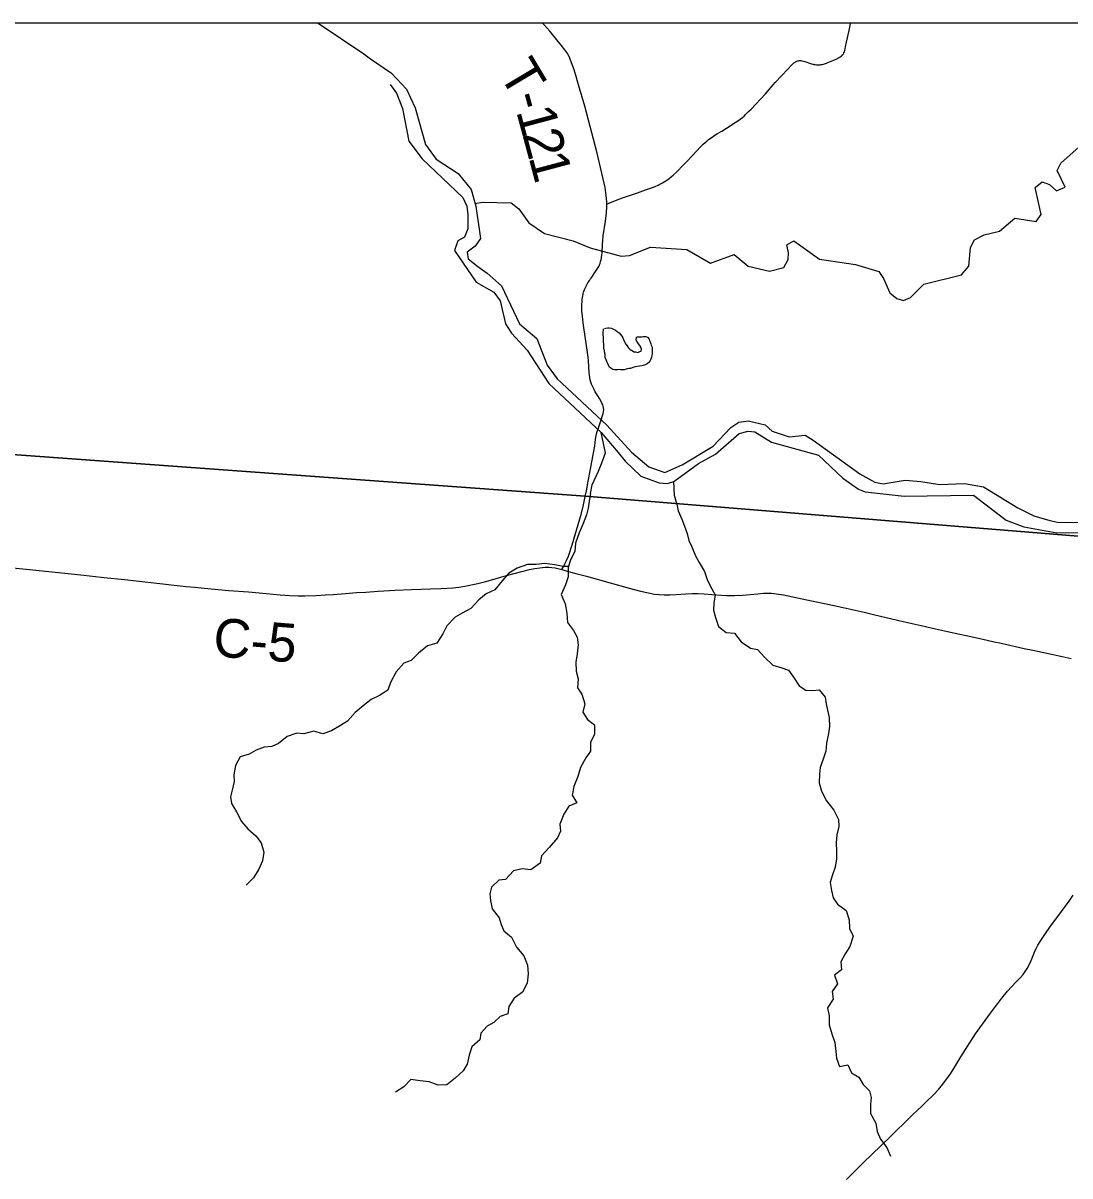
# Model space of a CAD drawing. Extents: x -1.4 to 35.4, y 0 to 22.
# Drawn here: x 6.004 to 7.544, y 18.159 to 19.855 of the extents above; entities that cross this region are included whole.
import ezdxf

# ---------------------------------------------------------------- set-up
doc = ezdxf.new("R2010")
doc.units = 0
for name, color, linetype in [('Default', 7, 'Continuous'), ('GM_X_County_Road', 7, 'Continuous'), ('GM_X_County_Road_Text', 7, 'Continuous'), ('GM_X_Major_River', 7, 'Continuous'), ('GM_X_Minor_Lake', 7, 'Continuous'), ('GM_X_Minor_River', 7, 'Continuous'), ('GM_X_Township_Road', 7, 'Continuous'), ('GM_X_Township_Road_Text', 7, 'Continuous'), ('SH_Border', 7, 'Continuous'), ('SH_Cut_Line', 7, 'Continuous')]:
    doc.layers.add(name, color=color, linetype=linetype)

msp = doc.modelspace()

# ---------------------------------------------------------------- linework, layer by layer
at = {"layer": 'Default'}
for points in [[(5.7921, 19.2341), (6.8306, 19.1588), (7.8947, 19.0723), (8.143, 19.049), (9, 18.9633), (9, 19.8546), (5.9686, 19.8546)], [(7.693, 16.8959), (7.7561, 17.6322), (7.8789, 18.9217), (7.8947, 19.0723), (6.8306, 19.1588), (5.7921, 19.2341), (4.2528, 19.417), (3.4459, 19.4989), (3.4296, 19.5001), (2.9037, 19.5459), (2.7894, 18.3098), (2.7365, 17.7956), (2.7172, 17.4718), (2.7109, 17.4025), (2.7066, 17.3545), (2.7033, 17.3163), (2.7006, 17.2849), (2.6906, 17.1666), (2.6843, 17.0961), (2.6688, 16.9164)]]:
    msp.add_lwpolyline(points, dxfattribs=at)
at = {"layer": 'GM_X_County_Road'}
for points in [[(5.9888, 19.0536), (6.0135, 19.0509), (6.0419, 19.0478), (6.0889, 19.0429), (6.1229, 19.0394), (6.1532, 19.0364), (6.1704, 19.0345), (6.205, 19.0304), (6.226, 19.028), (6.2439, 19.0261), (6.2563, 19.025), (6.2705, 19.0236), (6.3064, 19.0202), (6.3355, 19.0179), (6.3615, 19.0156), (6.3819, 19.0137), (6.3962, 19.0127), (6.4086, 19.0122), (6.4186, 19.0122), (6.4347, 19.0127), (6.449, 19.0136), (6.4602, 19.0143), (6.4781, 19.0157), (6.4942, 19.0169), (6.5079, 19.0177), (6.5265, 19.0189), (6.5512, 19.0205), (6.5754, 19.0216), (6.6026, 19.0226), (6.6187, 19.0231), (6.636, 19.0239), (6.6447, 19.0248), (6.6539, 19.0262), (6.6728, 19.0303), (6.6848, 19.0334), (6.7153, 19.042), (6.7375, 19.0481), (6.7489, 19.0509), (6.7568, 19.0525), (6.7641, 19.0535), (6.772, 19.0542), (6.7776, 19.0542), (6.7819, 19.0539), (6.7867, 19.0532), (6.7945, 19.0513), (6.7964, 19.0508)], [(6.7964, 19.0508), (6.8011, 19.0496), (6.8172, 19.0451), (6.8329, 19.041), (6.8676, 19.0315), (6.8957, 19.0237), (6.912, 19.0193), (6.9241, 19.0164), (6.9321, 19.0149), (6.9395, 19.014), (6.947, 19.0136), (6.9552, 19.0136), (6.9645, 19.0141), (6.9787, 19.0152), (6.9886, 19.0156), (6.9966, 19.0156), (7.0059, 19.0151), (7.017, 19.0141), (7.0313, 19.0131), (7.0388, 19.0128), (7.0512, 19.0128), (7.063, 19.0132), (7.0736, 19.014), (7.0847, 19.0153), (7.0933, 19.0161), (7.1007, 19.0163), (7.105, 19.0162), (7.1117, 19.0154), (7.1227, 19.0135), (7.164, 19.0048), (7.1877, 18.9998), (7.2102, 18.9949), (7.2411, 18.9881), (7.2568, 18.9844), (7.2985, 18.9746), (7.3252, 18.9686), (7.3464, 18.9637), (7.364, 18.9599), (7.3822, 18.9558), (7.3913, 18.9538), (7.4137, 18.9488), (7.4325, 18.9447), (7.4428, 18.9424), (7.4768, 18.9349), (7.4895, 18.9321), (7.5193, 18.9259), (7.546, 18.9199)], [(7.2152, 18.1538), (7.2409, 18.1791), (7.252, 18.19), (7.2666, 18.2043), (7.2796, 18.2168), (7.2885, 18.2255), (7.3004, 18.2372), (7.312, 18.2485), (7.32, 18.2562), (7.3254, 18.2614), (7.3322, 18.2678), (7.3436, 18.2791), (7.3504, 18.2864), (7.3568, 18.2939), (7.361, 18.2993), (7.3671, 18.3078), (7.3732, 18.3171), (7.379, 18.3267), (7.3835, 18.3341), (7.3936, 18.3505), (7.4053, 18.3681), (7.4153, 18.3823), (7.427, 18.3984), (7.4345, 18.4083), (7.4379, 18.4128), (7.444, 18.4206), (7.4523, 18.4307), (7.4581, 18.4372), (7.465, 18.4444), (7.4714, 18.4511), (7.475, 18.4552), (7.4783, 18.4596), (7.4812, 18.4642), (7.484, 18.4696), (7.4868, 18.4757), (7.4919, 18.4883), (7.4942, 18.4934), (7.4968, 18.4984), (7.501, 18.5053), (7.5069, 18.5142), (7.5145, 18.5248), (7.5315, 18.5478), (7.5429, 18.5633), (7.5488, 18.572)]]:
    msp.add_lwpolyline(points, dxfattribs=at)
at = {"layer": 'GM_X_Major_River'}
for points in [[(6.4382, 19.8546), (6.505, 19.8095), (6.5151, 19.8021), (6.5461, 19.7808), (6.568, 19.7575), (6.5807, 19.7298), (6.5958, 19.6762), (6.6116, 19.6542), (6.6442, 19.6333), (6.6631, 19.61), (6.6701, 19.5855), (6.677, 19.5378), (6.6688, 19.5266), (6.6572, 19.5174), (6.6585, 19.5078), (6.673, 19.4965), (6.6865, 19.487), (6.7077, 19.4679), (6.7342, 19.4121), (6.7599, 19.3906), (6.775, 19.3515), (6.7894, 19.3314), (6.8627, 19.2631), (6.899, 19.2235), (6.9244, 19.202), (6.9481, 19.1938), (6.9735, 19.205), (7.019, 19.2321), (7.0451, 19.2597), (7.057, 19.2674), (7.0708, 19.2697), (7.0957, 19.2635), (7.1061, 19.2545), (7.1307, 19.2459), (7.1543, 19.2484), (7.1663, 19.2413), (7.2347, 19.1918), (7.2569, 19.1795), (7.2693, 19.1769), (7.3018, 19.1823), (7.3245, 19.1806), (7.3522, 19.1758), (7.3891, 19.1776), (7.4167, 19.1724), (7.4673, 19.1415), (7.491, 19.13), (7.5144, 19.123), (7.5258, 19.1204), (7.601, 19.1202)], [(6.5439, 19.7641), (6.5534, 19.7514), (6.5621, 19.7291), (6.5716, 19.681), (6.5908, 19.655), (6.651, 19.5978), (6.6568, 19.5851), (6.6584, 19.5725), (6.6582, 19.5618), (6.6583, 19.5519), (6.6535, 19.5399), (6.6435, 19.5344), (6.6386, 19.5201), (6.6706, 19.4733), (6.6965, 19.459), (6.7057, 19.4463), (6.7137, 19.4122), (6.7225, 19.3983), (6.7455, 19.3735), (6.7774, 19.3244), (6.8545, 19.2523), (6.8793, 19.2232), (6.8896, 19.2104), (6.9127, 19.1882), (6.9398, 19.1784), (6.9516, 19.1774), (6.9611, 19.1802), (6.9975, 19.2068), (7.0225, 19.2207), (7.0574, 19.251), (7.0704, 19.2542), (7.0803, 19.2532), (7.105, 19.2381), (7.1741, 19.2191), (7.2099, 19.1855), (7.2327, 19.169), (7.2429, 19.1654), (7.3001, 19.1587), (7.402, 19.1602), (7.4502, 19.1237), (7.4762, 19.1136), (7.5247, 19.1048), (7.5787, 19.1055)], [(6.8386, 19.1629), (6.8411, 19.1754), (6.8505, 19.1955), (6.8551, 19.208), (6.8609, 19.2224), (6.8545, 19.2523)], [(6.9651, 19.1495), (6.962, 19.1596), (6.9611, 19.1802)]]:
    msp.add_lwpolyline(points, dxfattribs=at)
at = {"layer": 'GM_X_Minor_Lake'}
msp.add_lwpolyline([(6.8591, 19.4055), (6.8614, 19.4059), (6.864, 19.4066), (6.8663, 19.4066), (6.8697, 19.4058), (6.8735, 19.4039), (6.8754, 19.4027), (6.8781, 19.4008), (6.8807, 19.3989), (6.8826, 19.3966), (6.8849, 19.3943), (6.8864, 19.3916), (6.8871, 19.3893), (6.8886, 19.3859), (6.8905, 19.3824), (6.8924, 19.3798), (6.8943, 19.3775), (6.8965, 19.3752), (6.8984, 19.3733), (6.9003, 19.3725), (6.9026, 19.3713), (6.9049, 19.3709), (6.9083, 19.3701), (6.9113, 19.3716), (6.9133, 19.372), (6.9137, 19.3751), (6.9125, 19.3777), (6.911, 19.3804), (6.9091, 19.3827), (6.9076, 19.3854), (6.9061, 19.3873), (6.9058, 19.3899), (6.9069, 19.393), (6.9092, 19.393), (6.9123, 19.3933), (6.9145, 19.3933), (6.9168, 19.3937), (6.9199, 19.3936), (6.9225, 19.3925), (6.9252, 19.3898), (6.9255, 19.3879), (6.9266, 19.3856), (6.9274, 19.3826), (6.9281, 19.3807), (6.9289, 19.3788), (6.9293, 19.3768), (6.9292, 19.3742), (6.9296, 19.3719), (6.9292, 19.3692), (6.9288, 19.3651), (6.9284, 19.3632), (6.9276, 19.3605), (6.9261, 19.3575), (6.9245, 19.3552), (6.9219, 19.3533), (6.9192, 19.3518), (6.9162, 19.3511), (6.9142, 19.3507), (6.9108, 19.35), (6.9074, 19.3496), (6.9044, 19.3489), (6.9009, 19.3478), (6.8975, 19.3466), (6.8952, 19.3467), (6.8929, 19.3463), (6.891, 19.3455), (6.8884, 19.3448), (6.8857, 19.3448), (6.883, 19.3448), (6.8804, 19.3449), (6.8785, 19.3445), (6.8758, 19.3445), (6.8739, 19.3445), (6.8713, 19.3453), (6.8686, 19.3469), (6.8663, 19.3491), (6.8645, 19.3526), (6.8626, 19.3568), (6.8615, 19.3595), (6.8603, 19.3629), (6.8604, 19.3652), (6.86, 19.3671), (6.8596, 19.3694), (6.8593, 19.3713), (6.8593, 19.3732), (6.8585, 19.3754), (6.8585, 19.3785), (6.8582, 19.3804), (6.8582, 19.3827), (6.8578, 19.3853), (6.8578, 19.388), (6.8579, 19.3907), (6.8579, 19.3933), (6.8571, 19.3956), (6.8571, 19.3979), (6.8575, 19.3998), (6.8576, 19.4025), (6.8579, 19.4044), (6.858, 19.4047)], dxfattribs=at)
at = {"layer": 'GM_X_Minor_River'}
for points in [[(6.6691, 19.589), (6.6792, 19.5912), (6.7221, 19.5902), (6.7333, 19.5816), (6.748, 19.5608), (6.7708, 19.545), (6.8131, 19.5345), (6.8383, 19.5241), (6.8836, 19.512), (6.8958, 19.5128), (6.9268, 19.525), (6.9802, 19.5215), (7.0154, 19.5017), (7.0502, 19.5142), (7.0707, 19.497), (7.1021, 19.4898), (7.123, 19.495), (7.1294, 19.507), (7.13, 19.5165), (7.1276, 19.5283), (7.1379, 19.5345), (7.1757, 19.5071), (7.2283, 19.4997), (7.2629, 19.4894), (7.2699, 19.479), (7.279, 19.4579), (7.2894, 19.4493), (7.2992, 19.4468), (7.3092, 19.4511), (7.3293, 19.4708), (7.3843, 19.4843), (7.3955, 19.497), (7.3976, 19.5243), (7.4036, 19.5356), (7.4178, 19.5432), (7.4406, 19.5484), (7.4631, 19.5676), (7.4945, 19.5627), (7.5019, 19.5732), (7.4929, 19.6125), (7.5033, 19.621), (7.5138, 19.617), (7.5242, 19.6076), (7.5369, 19.6134), (7.5253, 19.6376), (7.5308, 19.6485), (7.5618, 19.6767)], [(6.8386, 19.1629), (6.8366, 19.1515), (6.8352, 19.1412), (6.8328, 19.1314), (6.828, 19.1186), (6.822, 19.105), (6.8164, 19.0899), (6.8154, 19.0774), (6.8091, 19.0654), (6.8058, 19.0537), (6.8059, 19.04), (6.8019, 19.0283), (6.7955, 19.0144), (6.8013, 19.0006), (6.8037, 18.9865), (6.8046, 18.9728), (6.8135, 18.9612), (6.819, 18.9516), (6.8206, 18.9401), (6.8192, 18.9269), (6.8171, 18.9148), (6.8176, 18.9014), (6.8204, 18.89), (6.8194, 18.8771), (6.8257, 18.8675), (6.8303, 18.8533), (6.8274, 18.8412), (6.834, 18.8304), (6.8445, 18.8223), (6.8446, 18.8089), (6.8387, 18.7965), (6.8388, 18.7836), (6.8318, 18.7739), (6.8239, 18.76), (6.8199, 18.7467), (6.8143, 18.732), (6.8117, 18.7192), (6.8183, 18.7076), (6.8068, 18.7029), (6.7994, 18.6909), (6.7934, 18.6762), (6.7947, 18.6659), (6.79, 18.6561), (6.7779, 18.6423), (6.7667, 18.63), (6.7646, 18.619), (6.7507, 18.6094), (6.7382, 18.6108), (6.7252, 18.6077), (6.7136, 18.595), (6.7037, 18.594), (6.6932, 18.5836), (6.6904, 18.5738), (6.6917, 18.5643), (6.6941, 18.5521), (6.7045, 18.5389), (6.7074, 18.529), (6.711, 18.5194), (6.7225, 18.5101), (6.7299, 18.4955), (6.7406, 18.4827), (6.746, 18.4693), (6.7469, 18.4564), (6.7455, 18.4427), (6.7384, 18.4292), (6.7261, 18.4203), (6.7183, 18.4083), (6.7169, 18.3977), (6.7058, 18.3938), (6.6962, 18.3848), (6.6866, 18.3793), (6.6772, 18.3693), (6.6759, 18.3594), (6.6643, 18.349), (6.6603, 18.3365), (6.6574, 18.3237), (6.6515, 18.3139), (6.6395, 18.3028), (6.6275, 18.2931), (6.6146, 18.2926), (6.6014, 18.2975), (6.5881, 18.2989), (6.5745, 18.301), (6.5641, 18.2902), (6.5517, 18.2821)], [(6.9651, 19.1495), (6.9677, 19.1371), (6.9731, 19.1248), (6.9771, 19.1145), (6.9807, 19.1038), (6.9835, 19.0938), (6.9875, 19.0843), (6.9929, 19.0712), (6.9984, 19.0612), (7.0065, 19.0478), (7.0101, 19.0363), (7.0145, 19.0267), (7.0222, 19.0136), (7.02, 19.0012), (7.0195, 18.9909), (7.0227, 18.9802), (7.027, 18.9672), (7.0382, 18.9582), (7.0507, 18.9572), (7.0603, 18.9445), (7.0742, 18.9355), (7.0844, 18.9334), (7.0944, 18.9218), (7.1067, 18.9105), (7.1203, 18.9061), (7.1301, 18.9028), (7.1375, 18.8924), (7.1456, 18.8797), (7.1553, 18.8734), (7.1656, 18.8732), (7.1751, 18.8738), (7.184, 18.8634), (7.1853, 18.8535), (7.1874, 18.8439), (7.1899, 18.8332), (7.1904, 18.8199), (7.189, 18.8097), (7.1857, 18.7957), (7.1847, 18.7839), (7.1811, 18.7722), (7.1766, 18.7598), (7.1757, 18.7499), (7.1751, 18.7374), (7.1786, 18.7248), (7.1859, 18.7109), (7.1967, 18.6971), (7.2036, 18.6832), (7.2038, 18.673), (7.2013, 18.6605), (7.1999, 18.6495), (7.2008, 18.6362), (7.2006, 18.6252), (7.1988, 18.6134), (7.194, 18.6006), (7.1911, 18.5904), (7.1932, 18.5789), (7.1956, 18.5683), (7.2019, 18.5586), (7.215, 18.5493), (7.2193, 18.5355), (7.2198, 18.5229), (7.2249, 18.5118), (7.2204, 18.4967), (7.2134, 18.4855), (7.2067, 18.4738), (7.208, 18.462), (7.1976, 18.4542), (7.2019, 18.4416), (7.1941, 18.4304), (7.1957, 18.4189), (7.1871, 18.4062), (7.1899, 18.3944), (7.19, 18.3811), (7.1936, 18.3681), (7.1979, 18.3551), (7.1995, 18.3421), (7.2005, 18.3322), (7.2052, 18.32), (7.2174, 18.3224), (7.2224, 18.3105), (7.2333, 18.3042), (7.2396, 18.2938), (7.2489, 18.2841), (7.2517, 18.2742), (7.2504, 18.2644), (7.2505, 18.2511), (7.2586, 18.2365), (7.2606, 18.2243), (7.2653, 18.2132), (7.2746, 18.2008), (7.28, 18.1882)], [(6.8063, 19.0556), (6.7982, 19.0553), (6.7861, 19.0579), (6.7717, 19.0597), (6.7588, 19.0584), (6.7459, 19.0583), (6.731, 19.0529), (6.7187, 19.0455), (6.7086, 19.0343), (6.6977, 19.0212), (6.6851, 19.0154), (6.6743, 19.0065), (6.6626, 18.9938), (6.65, 18.9869), (6.6396, 18.981), (6.6272, 18.9683), (6.6216, 18.9563), (6.6126, 18.9424), (6.5989, 18.9389), (6.5858, 18.9277), (6.5749, 18.9169), (6.5638, 18.9133), (6.5526, 18.9003), (6.5443, 18.8848), (6.5403, 18.8735), (6.528, 18.8658), (6.5161, 18.8596), (6.5041, 18.8503), (6.4922, 18.8407), (6.4809, 18.828), (6.4709, 18.8213), (6.4575, 18.8136), (6.4448, 18.8093), (6.4316, 18.8134), (6.4171, 18.8095), (6.4065, 18.8101), (6.3924, 18.8054), (6.3796, 18.795), (6.3697, 18.7907), (6.3586, 18.7898), (6.3468, 18.7851), (6.3364, 18.7796), (6.3234, 18.7753), (6.3164, 18.7629), (6.3138, 18.7492), (6.3144, 18.7393), (6.3115, 18.7265), (6.309, 18.7167), (6.3103, 18.7068), (6.318, 18.6944), (6.325, 18.6802), (6.3343, 18.6698), (6.3462, 18.6593), (6.3543, 18.6489), (6.3582, 18.6351), (6.3561, 18.6223), (6.3509, 18.6102), (6.3427, 18.5974), (6.3322, 18.5866)]]:
    msp.add_lwpolyline(points, dxfattribs=at)
at = {"layer": 'GM_X_Township_Road'}
for points in [[(6.8628, 19.5887), (6.8628, 19.5917), (6.8618, 19.601), (6.86, 19.6126), (6.8487, 19.6631), (6.8303, 19.7322), (6.8208, 19.7638), (6.8166, 19.7792), (6.8137, 19.7886), (6.8109, 19.7963), (6.8084, 19.8029), (6.8051, 19.8093), (6.8008, 19.8154), (6.7955, 19.822), (6.787, 19.8326), (6.7786, 19.8425), (6.7701, 19.8523), (6.7682, 19.8546)], [(7.1664, 19.7939), (7.1672, 19.7937), (7.1692, 19.7935), (7.1712, 19.7933), (7.1732, 19.7932), (7.1752, 19.7932), (7.1767, 19.7933), (7.1781, 19.7936), (7.1793, 19.7938), (7.1812, 19.7943), (7.1829, 19.7947), (7.1857, 19.7956), (7.188, 19.7965), (7.1927, 19.7984), (7.2002, 19.8016), (7.2044, 19.8039), (7.2059, 19.8048), (7.2073, 19.8058), (7.2082, 19.8065), (7.2099, 19.8082), (7.2107, 19.8093), (7.2112, 19.8104), (7.2116, 19.8112), (7.2121, 19.8125), (7.2128, 19.8148), (7.2133, 19.8168), (7.2138, 19.8197), (7.2153, 19.8263), (7.2191, 19.8434), (7.2214, 19.8537), (7.2216, 19.8546)], [(6.8628, 19.5887), (6.8645, 19.5894), (6.8753, 19.5935), (6.8856, 19.5974), (6.8961, 19.6011), (6.9079, 19.6051), (6.9196, 19.6091), (6.9255, 19.6111), (6.9301, 19.6128), (6.934, 19.6143), (6.9381, 19.6162), (6.9408, 19.6176), (6.9446, 19.6197), (6.9471, 19.6212), (6.9509, 19.6237), (6.9542, 19.6262), (6.9578, 19.6289), (6.9602, 19.6311), (6.9656, 19.6359), (6.9752, 19.6455), (6.9803, 19.6509), (6.9875, 19.6587), (7.0012, 19.673), (7.0046, 19.6764), (7.0072, 19.6788), (7.0099, 19.6811), (7.0124, 19.6832), (7.016, 19.6858), (7.0194, 19.6882), (7.0246, 19.6915), (7.0318, 19.6958), (7.0387, 19.6998), (7.0517, 19.7081), (7.0556, 19.7108), (7.0589, 19.7131), (7.0623, 19.7158), (7.0645, 19.7178), (7.0668, 19.72), (7.0713, 19.7243), (7.0749, 19.7278), (7.0959, 19.7505), (7.1104, 19.7671), (7.1291, 19.787), (7.1342, 19.7925), (7.1363, 19.7945), (7.1379, 19.7959), (7.1391, 19.7968), (7.1401, 19.7975), (7.1411, 19.798), (7.1422, 19.7985), (7.1435, 19.7989), (7.1448, 19.7992)], [(7.1448, 19.7992), (7.1463, 19.7994), (7.1481, 19.7993), (7.1497, 19.7991), (7.1518, 19.7986), (7.1539, 19.7979), (7.1622, 19.7951), (7.1637, 19.7946), (7.1656, 19.794), (7.1664, 19.7939)], [(6.8309, 19.1583), (6.8327, 19.1668), (6.8352, 19.1807), (6.8387, 19.1985), (6.8421, 19.2169), (6.8448, 19.2328), (6.8461, 19.2425), (6.847, 19.2478), (6.8475, 19.2504), (6.8485, 19.2537), (6.8493, 19.2564), (6.8532, 19.2681), (6.8573, 19.2805), (6.858, 19.2833), (6.8582, 19.2861), (6.8579, 19.2888), (6.8573, 19.2912), (6.8566, 19.2933), (6.8555, 19.2958), (6.8539, 19.2989), (6.8517, 19.3024), (6.8492, 19.3065), (6.8457, 19.3124), (6.8439, 19.3156), (6.842, 19.3195), (6.8403, 19.3235), (6.8393, 19.3265), (6.8383, 19.3301), (6.8376, 19.3331), (6.8372, 19.3368), (6.8369, 19.3406), (6.8363, 19.3491), (6.8357, 19.3584), (6.8349, 19.3665), (6.8304, 19.397), (6.8295, 19.4036), (6.8281, 19.4138), (6.8267, 19.4234), (6.826, 19.4309), (6.8258, 19.4336), (6.8258, 19.4371), (6.8259, 19.4391), (6.826, 19.441), (6.8262, 19.4439), (6.8266, 19.4484), (6.8269, 19.4508), (6.8273, 19.4535), (6.8277, 19.4552), (6.8281, 19.457), (6.8285, 19.4588), (6.8293, 19.4611), (6.8299, 19.4628), (6.8306, 19.4645), (6.8312, 19.4658), (6.8321, 19.4677), (6.8335, 19.4704), (6.8349, 19.4726), (6.836, 19.4744), (6.837, 19.476), (6.8382, 19.4778), (6.8394, 19.4795), (6.8472, 19.4907), (6.8508, 19.4968), (6.8519, 19.4991), (6.8527, 19.5011), (6.8535, 19.5038), (6.8541, 19.5063), (6.8549, 19.5098), (6.8555, 19.5133), (6.8559, 19.5172), (6.8564, 19.5296), (6.8567, 19.5346), (6.8574, 19.5416), (6.8606, 19.5633), (6.8621, 19.5756), (6.8629, 19.5849), (6.8628, 19.5887)], [(6.7964, 19.0508), (6.7992, 19.0558), (6.8011, 19.0591), (6.8035, 19.0642), (6.8062, 19.0705), (6.8116, 19.0871), (6.8206, 19.117), (6.8254, 19.1338), (6.8284, 19.146), (6.8309, 19.1583)]]:
    msp.add_lwpolyline(points, dxfattribs=at)
at = {"layer": 'SH_Border'}
msp.add_lwpolyline([(9, 19.8546), (2.2, 19.8546), (2.2, 13.0546), (9, 13.0546)], close=True, dxfattribs=at)
at = {"layer": 'SH_Cut_Line'}
msp.add_lwpolyline([(9, 18.9633), (9, 19.8546), (2.2, 19.8546), (2.2, 19.619), (2.3668, 19.6046), (2.4279, 19.5993), (2.9037, 19.5459), (3.4296, 19.5001), (3.4459, 19.4989), (4.2528, 19.417), (5.7921, 19.2341), (6.8306, 19.1588), (7.8947, 19.0723), (8.143, 19.049)], close=True, dxfattribs=at)
msp.add_lwpolyline([(9, 13.0546), (9, 18.9633), (8.143, 19.049), (7.8947, 19.0723), (6.8306, 19.1588), (5.7921, 19.2341), (4.2528, 19.417), (3.4459, 19.4989), (3.4296, 19.5001), (2.9037, 19.5459), (2.7894, 18.3098), (2.7365, 17.7956), (2.7172, 17.4718), (2.7109, 17.4025), (2.7066, 17.3545), (2.7033, 17.3163), (2.7006, 17.2849), (2.6906, 17.1666), (2.6843, 17.0961), (2.6688, 16.9164)], dxfattribs=at)

# ---------------------------------------------------------------- texts
at = {"layer": 'GM_X_County_Road_Text'}
msp.add_text('C-5', height=0.05682, rotation=355.4211, dxfattribs=at).set_placement((6.2822, 18.9236))
at = {"layer": 'GM_X_Township_Road_Text'}
for s, rotation, p in [('T', 300.8958, (6.7028, 19.7802)), ('-', 285.301, (6.723, 19.7475)), ('1', 285.0669, (6.7291, 19.7251)), ('2', 284.9696, (6.7382, 19.6913)), ('1', 284.9482, (6.7473, 19.6575))]:
    msp.add_text(s, height=0.0568, rotation=rotation, dxfattribs=at).set_placement(p)

doc.saveas('drawing.dxf')
